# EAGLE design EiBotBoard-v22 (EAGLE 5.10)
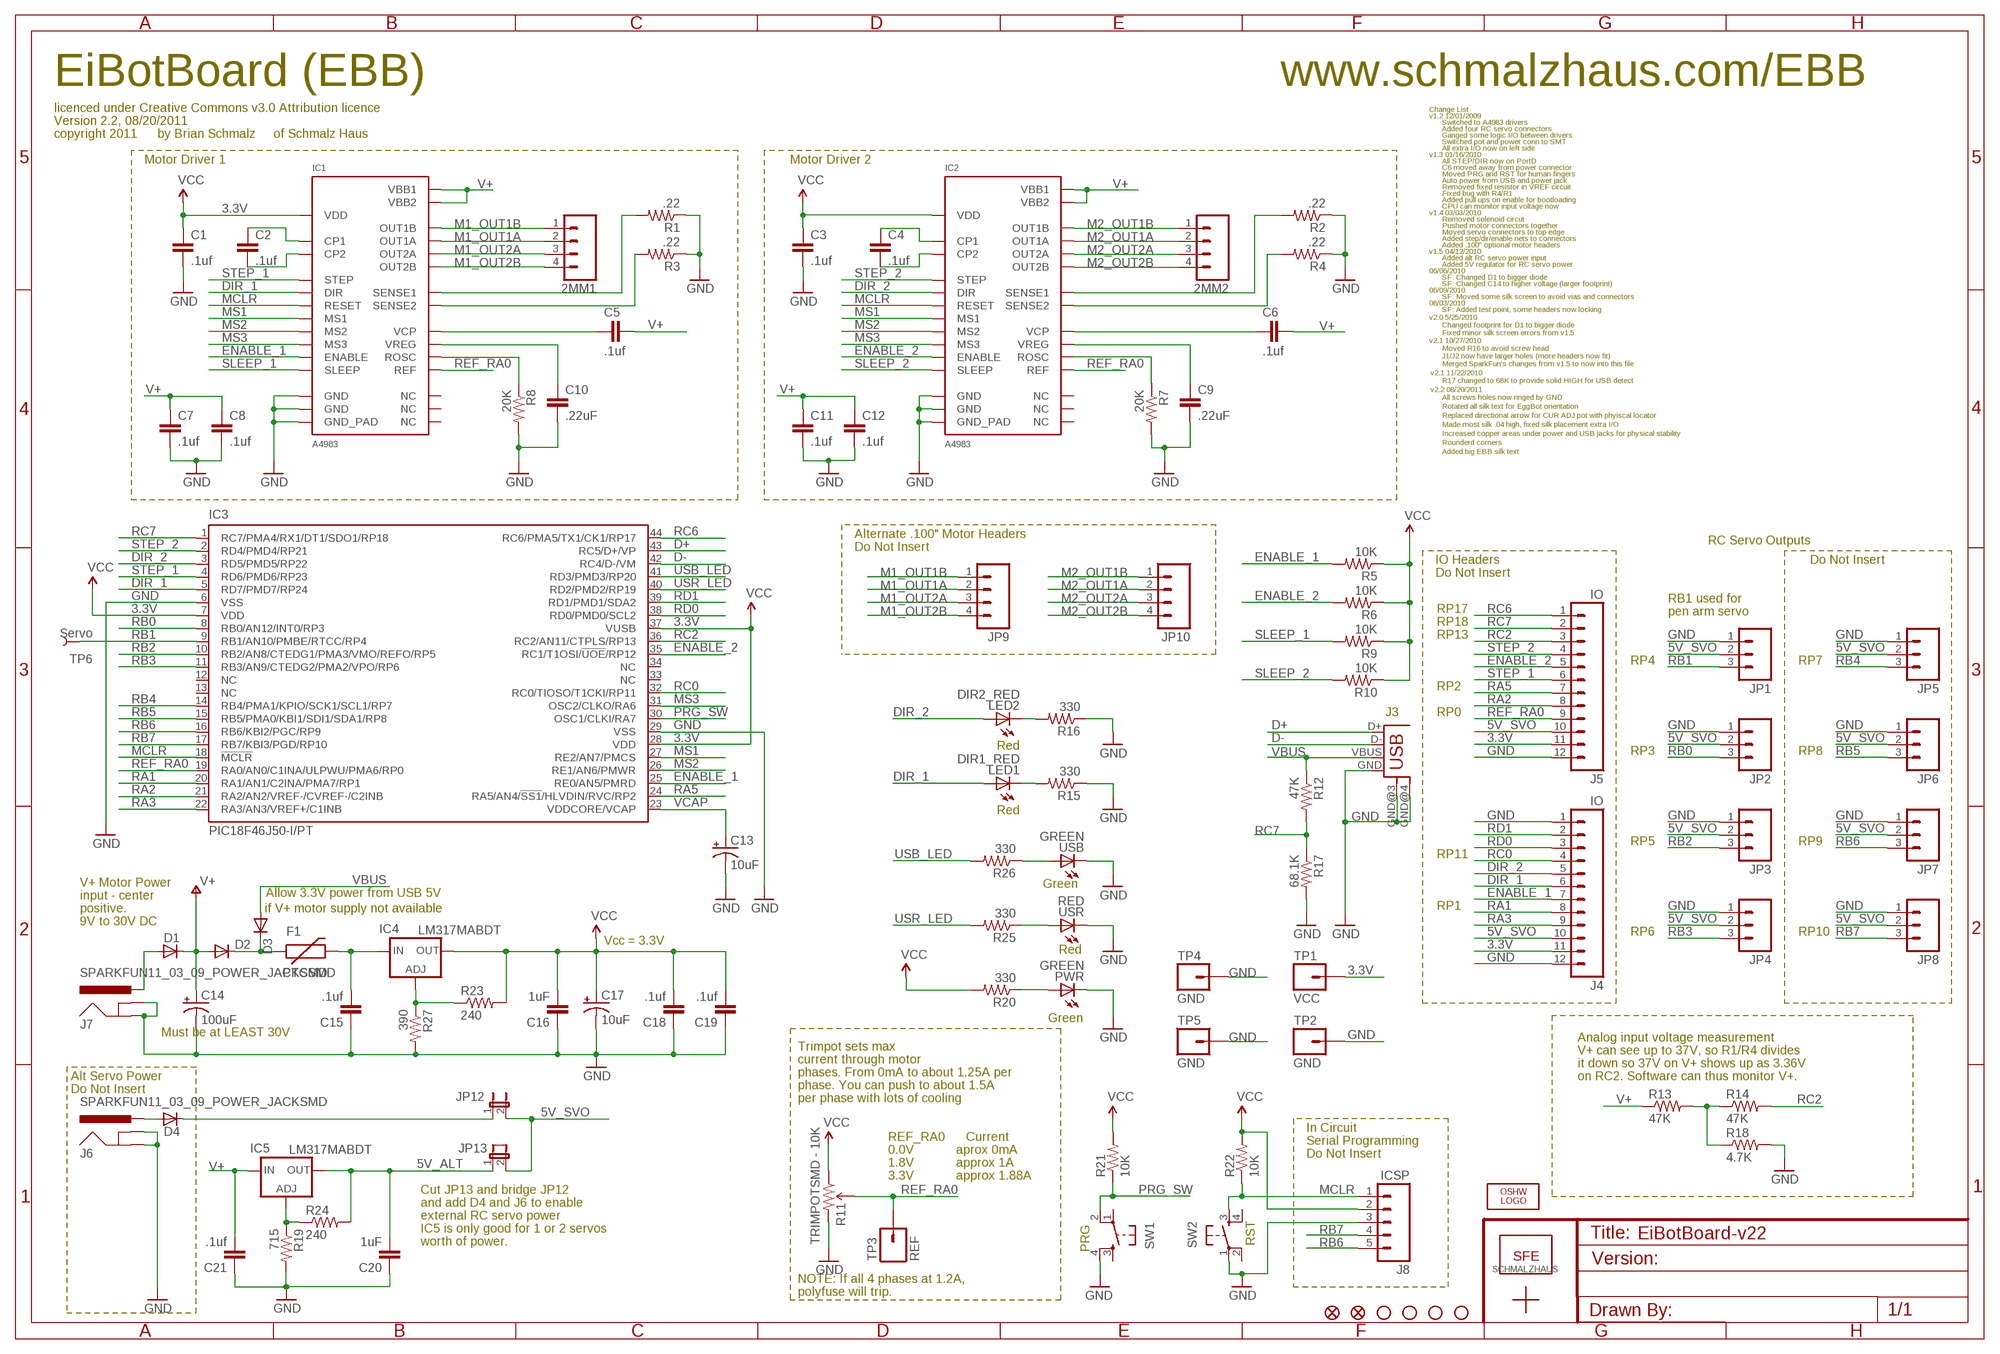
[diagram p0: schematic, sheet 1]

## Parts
2MM1  SCHMALZHAUS_M04  [SCHMALZHAUS_SCREWTERMINAL-3.5MM-4_LOCK]
2MM2  SCHMALZHAUS_M04  [SCHMALZHAUS_SCREWTERMINAL-3.5MM-4_LOCK]
C1  .1uf  CAP0603  [0603]
C2  .1uf  CAP0603  [0603]
C3  .1uf  CAP0603  [0603]
C4  .1uf  CAP0603  [0603]
C5  .1uf  CAP0603  [0603]
C6  .1uf  CAP0603  [0603]
C7  .1uf  CAP0603  [0603]
C8  .1uf  CAP0603  [0603]
C9  .22uF  CAP0603  [0603]
C10  .22uF  CAP0603  [0603]
C11  .1uf  CAP0603  [0603]
C12  .1uf  CAP0603  [0603]
C13  10uF  CAP_POL1206  [EIA3216]
C14  100uF  CAP_POLG  [PANASONIC_G]
C15  .1uf  CAP0603  [0603]
C16  1uF  CAP0603  [0603]
C17  10uF  CAP_POL1206  [EIA3216]
C18  .1uf  CAP0603  [0603]
C19  .1uf  CAP0603  [0603]
C20  1uF  CAP0603  [0603]
C21  .1uf  CAP0603  [0603]
D1  DIODE-DO214AC  [DO214AC]
D2  DIODESMA  [SMA-DIODE]
D3  DIODESMA  [SMA-DIODE]
D4  CGRM4001-G  [SOD-123_MINI-SMA]
F1  PTCSMD  [PTC-1206]
IC1  A4983  [QFN28]
IC2  A4983  [QFN28]
IC3  PIC18F46J50-I/PT  PIC18F4J50  [TQFP44]
IC4  LM317MABDT  [DPACK]
IC5  LM317MABDT  [DPACK]
J3  SCHMALZHAUS_USBSMD  [SCHMALZHAUS_USB-MINIB]
J4  IO  M12PTH  [1X12]
J5  IO  M12PTH  [1X12]
J6  SPARKFUN11_03_09_POWER_JACKSMD  [SPARKFUN11_03_09_POWER_JACK_SMD]
J7  SPARKFUN11_03_09_POWER_JACKSMD  [SPARKFUN11_03_09_POWER_JACK_SMD]
J8  ICSP  M05_WIDENOSILK  [1X05_NOSILK]
JP1  M03LOCK_NO_SILK  [1X03_LOCK_NO_SILK]
JP2  M031X03_NO_SILK  [1X03_NO_SILK]
JP3  M031X03_NO_SILK  [1X03_NO_SILK]
JP4  M031X03_NO_SILK  [1X03_NO_SILK]
JP5  M031X03_NO_SILK  [1X03_NO_SILK]
JP6  M031X03_NO_SILK  [1X03_NO_SILK]
JP7  M031X03_NO_SILK  [1X03_NO_SILK]
JP8  M031X03_NO_SILK  [1X03_NO_SILK]
JP9  M04POLAR  [MOLEX-1X4]
JP10  M04POLAR  [MOLEX-1X4]
JP11  LOGO-SFENEW  [SFE-NEW-WEBLOGO]
JP12  JUMPER-2SMD-NO  [SJ_2S-NO]
JP13  JUMPER-2SMD-NO  [SJ_2S-NO]
JP14  FIDUCIAL1X2  [FIDUCIAL-1X2]
JP15  FIDUCIAL1X2  [FIDUCIAL-1X2]
LED1  DIR1_RED  LED0603  [LED-0603]
LED2  DIR2_RED  LED0603  [LED-0603]
LOGO1  OSHW_LOGO_8MILX0100-NT  [OSHW_8X100_NOTEXT]
PWR  GREEN  LED0603  [LED-0603]
R1  .22  R-US_R0805  [R0805]
R2  .22  R-US_R0805  [R0805]
R3  .22  R-US_R0805  [R0805]
R4  .22  R-US_R0805  [R0805]
R5  10K  R-US_R0603  [R0603]
R6  10K  R-US_R0603  [R0603]
R7  20K  R-US_R0603  [R0603]
R8  20K  R-US_R0603  [R0603]
R9  10K  R-US_R0603  [R0603]
R10  10K  R-US_R0603  [R0603]
R11  TRIMPOTSMD - 10K  TRIMPOTSMD  [TRIMPOT-3MM]
R12  47K  R-US_R0603  [R0603]
R13  47K  R-US_R0603  [R0603]
R14  47K  R-US_R0603  [R0603]
R15  330  R-US_R0603  [R0603]
R16  330  R-US_R0603  [R0603]
R17  68.1K  R-US_R0603  [R0603]
R18  4.7K  R-US_R0603  [R0603]
R19  715  R-US_R0603  [R0603]
R20  330  R-US_R0603  [R0603]
R21  10K  R-US_R0603  [R0603]
R22  10K  R-US_R0603  [R0603]
R23  240  R-US_R0603  [R0603]
R24  240  R-US_R0603  [R0603]
R25  330  R-US_R0603  [R0603]
R26  330  R-US_R0603  [R0603]
R27  390  R-US_R0603  [R0603]
SW1  PRG  TAC_SWITCHSND  [TACTILE_SWITCH_SMD]
SW2  RST  TAC_SWITCHSND  [TACTILE_SWITCH_SMD]
TP1  VCC  M01_WIDENOSLIK  [1X01_NOSILK]
TP2  GND  M01_WIDENOSLIK  [1X01_NOSILK]
TP3  REF  M01PTH  [1X01]
TP4  GND  M01_WIDENOSLIK  [1X01_NOSILK]
TP5  GND  M01_WIDENOSLIK  [1X01_NOSILK]
TP6  Servo  TEST-POINT3X5  [PAD.03X.05]
U$1  SCHMALZHAUSSCHMALZHAUS_SMALL  [SCHMALZHAUS_SMALL]
U$2  STAND-OFF  [STAND-OFF]
U$3  STAND-OFF  [STAND-OFF]
U$4  STAND-OFF  [STAND-OFF]
U$5  STAND-OFF  [STAND-OFF]
USB  GREEN  LED0603  [LED-0603]
USR  RED  LED0603  [LED-0603]

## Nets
3.3V: C1.1 C3.1 C16.2 C17.A(+) C18.2 C19.2 IC1.P$15(VDD) IC2.P$15(VDD) IC3.7(VDD) IC3.28(VDD) IC3.37(VUSB) IC4.4(OUT) J4.11 J5.11 J8.2 R5.1 R6.1 R9.1 R10.1 R11.1(CCW) R20.2 R21.2 R22.2 R23.2 TP1.1 ; supply symbol labelled VCC
5V_ALT: C20.2 IC5.4(OUT) JP13.1 R24.2
5V_SVO: J4.10 J5.10 JP1.2 JP2.2 JP3.2 JP4.2 JP5.2 JP6.2 JP7.2 JP8.2 JP12.2 JP13.2
D+: IC3.43(RC5/D+/VP) J3.D+
D-: IC3.42(RC4/D-/VM) J3.D-
DIR_1: IC1.P$19(DIR) IC3.5(RD7/PMD7/RP24) J4.6 LED1.A
DIR_2: IC2.P$19(DIR) IC3.3(RD5/PMD5/RP22) J4.5 LED2.A
ENABLE_1: IC1.P$2(ENABLE) IC3.25(RE0/AN5/PMRD) J4.7 R5.2
ENABLE_2: IC2.P$2(ENABLE) IC3.35(RC1/T1OSI/!UOE!/RP12) J5.5 R6.2
GND: C1.2 C3.2 C7.2 C8.2 C9.2 C10.2 C11.2 C12.2 C13.C(-) C14.- C15.1 C16.1 C17.C(-) C18.1 C19.1 C20.1 C21.1 IC1.P$3(GND) IC1.P$18(GND) IC1.P$29(GND_PAD) IC2.P$3(GND) IC2.P$18(GND) IC2.P$29(GND_PAD) IC3.6(VSS) IC3.29(VSS) J3.GND J3.GND@3(GND) J3.GND@4(GND) J4.1 J4.12 J5.12 J6.GND(GNDBREAK) J6.P$4(GND) J7.GND(GNDBREAK) J7.P$4(GND) J8.3 JP1.1 JP2.1 JP3.1 JP4.1 JP5.1 JP6.1 JP7.1 JP8.1 PWR.C R1.1 R2.1 R3.1 R4.1 R7.2 R8.2 R11.3(CW) R15.1 R16.1 R17.2 R18.2 R19.2 R27.2 SW1.4 SW2.1 TP2.1 TP4.1 TP5.1 USB.C USR.C
M1_OUT1A: 2MM1.2 IC1.P$24(OUT1A) JP9.2
M1_OUT1B: 2MM1.1 IC1.P$21(OUT1B) JP9.1
M1_OUT2A: 2MM1.3 IC1.P$26(OUT2A) JP9.3
M1_OUT2B: 2MM1.4 IC1.P$1(OUT2B) JP9.4
M2_OUT1A: 2MM2.2 IC2.P$24(OUT1A) JP10.2
M2_OUT1B: 2MM2.1 IC2.P$21(OUT1B) JP10.1
M2_OUT2A: 2MM2.3 IC2.P$26(OUT2A) JP10.3
M2_OUT2B: 2MM2.4 IC2.P$1(OUT2B) JP10.4
MCLR: IC1.P$12(RESET) IC2.P$12(RESET) IC3.18(!MCLR!) J8.1 R22.1 SW2.3
MS1: IC1.P$9(MS1) IC2.P$9(MS1) IC3.27(RE2/AN7/PMCS)
MS2: IC1.P$10(MS2) IC2.P$10(MS2) IC3.26(RE1/AN6/PMWR)
MS3: IC1.P$11(MS3) IC2.P$11(MS3) IC3.31(OSC2/CLKO/RA6)
N$2: D2.C D3.C F1.1
N$3: C2.1 IC1.P$4(CP1)
N$4: R13.2 R14.1 R18.1
N$5: C2.2 IC1.P$5(CP2)
N$6: D1.A J7.VIN0(PWR)
N$7: D4.A J6.VIN0(PWR)
N$8: IC5.1(ADJ) R19.1 R24.1
N$9: IC4.1(ADJ) R23.1 R27.1
N$10: D4.C JP12.1
N$16: C4.1 IC2.P$4(CP1)
N$17: C4.2 IC2.P$5(CP2)
N$19: IC1.P$13(ROSC) R8.1
N$20: C10.1 IC1.P$8(VREG)
N$21: C5.1 IC1.P$6(VCP)
N$26: LED2.C R16.2
N$27: PWR.A R20.1
N$29: R26.1 USB.A
N$30: R25.1 USR.A
N$31: IC1.P$27(SENSE2) R3.2
N$32: IC1.P$23(SENSE1) R1.2
N$35: LED1.C R15.2
N$36: C15.2 F1.2 IC4.3(IN)
N$41: C6.1 IC2.P$6(VCP)
N$43: IC2.P$23(SENSE1) R2.2
N$44: IC2.P$27(SENSE2) R4.2
N$45: C9.1 IC2.P$8(VREG)
N$48: IC2.P$13(ROSC) R7.1
PRG_SW: IC3.30(OSC1/CLKI/RA7) R21.1 SW1.2
RA1: IC3.20(RA1/AN1/C2INA/PMA7/RP1) J4.8
RA2: IC3.21(RA2/AN2/VREF-/CVREF-/C2INB) J5.8
RA3: IC3.22(RA3/AN3/VREF+/C1INB) J4.9
RA5: IC3.24(RA5/AN4/!SS1!/HLVDIN/RVC/RP2) J5.7
RB0: IC3.8(RB0/AN12/INT0/RP3) JP2.3
RB1: IC3.9(RB1/AN10/PMBE/RTCC/RP4) JP1.3 TP6.P$1
RB2: IC3.10(RB2/AN8/CTEDG1/PMA3/VMO/REFO/RP5) JP3.3
RB3: IC3.11(RB3/AN9/CTEDG2/PMA2/VPO/RP6) JP4.3
RB4: IC3.14(RB4/PMA1/KPIO/SCK1/SCL1/RP7) JP5.3
RB5: IC3.15(RB5/PMA0/KBI1/SDI1/SDA1/RP8) JP6.3
RB6: IC3.16(RB6/KBI2/PGC/RP9) J8.5 JP7.3
RB7: IC3.17(RB7/KBI3/PGD/RP10) J8.4 JP8.3
RC0: IC3.32(RC0/TIOSO/T1CKI/RP11) J4.4
RC2: IC3.36(RC2/AN11/CTPLS/RP13) J5.3 R14.2
RC6: IC3.44(RC6/PMA5/TX1/CK1/RP17) J5.1
RC7: IC3.1(RC7/PMA4/RX1/DT1/SDO1/RP18) J5.2 R12.2 R17.1
RD0: IC3.38(RD0/PMD0/SCL2) J4.3
RD1: IC3.39(RD1/PMD1/SDA2) J4.2
REF_RA0: IC1.P$17(REF) IC2.P$17(REF) IC3.19(RA0/AN0/C1INA/ULPWU/PMA6/RP0) J5.9 R11.2(WIPER) TP3.1
SLEEP_1: IC1.P$14(SLEEP) R9.2
SLEEP_2: IC2.P$14(SLEEP) R10.2
STEP_1: IC1.P$16(STEP) IC3.4(RD6/PMD6/RP23) J5.6
STEP_2: IC2.P$16(STEP) IC3.2(RD4/PMD4/RP21) J5.4
USB_LED: IC3.41(RD3/PMD3/RP20) R26.2
USR_LED: IC3.40(RD2/PMD2/RP19) R25.2
V+: C5.2 C6.2 C7.1 C8.1 C11.1 C12.1 C14.+ C21.2 D1.C D2.A IC1.P$22(VBB1) IC1.P$28(VBB2) IC2.P$22(VBB1) IC2.P$28(VBB2) IC5.3(IN) R13.1
VBUS: D3.A J3.VBUS R12.1
VCAP: C13.A(+) IC3.23(VDDCORE/VCAP)
Unconnected: IC1.P$7(NC) IC1.P$20(NC) IC1.P$25(NC) IC2.P$7(NC) IC2.P$20(NC) IC2.P$25(NC) IC3.12(NC) IC3.13(NC) IC3.33(NC) IC3.34(NC) SW1.1 SW1.3 SW2.2 SW2.4

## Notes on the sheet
- EiBotBoard (EBB) | www.schmalzhaus.com/EBB
- licenced under Creative Commons v3.0 Attribution licence | Change List
- v1.2 12/01/2009
- Version 2.2, 08/20/2011 | Switched to A4983 drivers
- Added four RC servo connectors
- copyright 2011 | by Brian Schmalz | of Schmalz Haus | Ganged some logic I/O between drivers
- Switched pot and power conn to SMT
- All extra I/O now on left side
- v1.3 01/16/2010
- Motor Driver 1 | Motor Driver 2 | All STEP/DIR now on PortD
- C6 moved away from power connector
- Moved PRG and RST for human fingers
- Auto power from USB and power jack
- Removed fixed resistor in VREF circuit
- Fixed bug with R4/R1
- Added pull ups on enable for bootloading
- CPU can monitor input voltage now
- v1.4 03/03/2010
- Removed solenoid circut
- Pushed motor connectors together
- Moved servo connectors to top edge
- Added step/dir/enable nets to connectors
- Added .100" optional motor headers
- v1.5 04/12/2010
- Added alt RC servo power input
- Added 5V regulator for RC servo power
- 06/06/2010
- SF: Changed D1 to bigger diode
- SF: Changed C14 to higher voltage (larger footprint)
- 06/09/2010
- SF: Moved some silk screen to avoid vias and connectors
- 08/03/2010
- SF: Added test point, some headers now locking
- v2.0 5/25/2010
- Changed footprint for D1 to bigger diode
- Fixed minor silk screen errors from v1.5
- v2.1 10/27/2010
- Moved R16 to avoid screw head
- J1/J2 now have larger holes (more headers now fit)
- Merged SparkFun's changes from v1.5 to now into this file
- v2.1 11/22/2010
- R17 changed to 68K to provide solid HIGH for USB detect
- v2.2 08/20/2011
- All screws holes now ringed by GND
- Rotated all silk text for EggBot orientation
- Replaced directional arrow for CUR ADJ pot with phyiscal locator
- Made most silk .04 high, fixed silk placement extra I/O
- Increased copper areas under power and USB jacks for physical stability
- Rounderd corners
- Added big EBB silk text
- Alternate .100" Motor Headers
- RC Servo Outputs
- Do Not Insert
- IO Headers | Do Not Insert
- Do Not Insert
- RB1 used for
- RP17 | pen arm servo
- RP18
- RP13
- RP4 | RP7
- RP2
- J3 | RP0
- Red
- RP3 | RP8
- Red
- RP5 | RP9
- RP11
- V+ Motor Power | Green
- input - center | Allow 3.3V power from USB 5V
- positive. | if V+ motor supply not available | RP1
- 9V to 30V DC
- RP6 | RP10
- Vcc = 3.3V | Red
- Green
- Must be at LEAST 30V
- Analog input voltage measurement
- Trimpot sets max
- V+ can see up to 37V, so R1/R4 divides
- current through motor
- it down so 37V on V+ shows up as 3.36V
- phases. From 0mA to about 1.25A per
- Alt Servo Power | on RC2. Software can thus monitor V+.
- phase. You can push to about 1.5A
- Do Not Insert
- per phase with lots of cooling
- In Circuit
- REF_RA0      Current
- Serial Programming
- 0.0V            aprox 0mA
- Do Not Insert
- 1.8V            approx 1A
- 3.3V            approx 1.88A
- Cut JP13 and bridge JP12
- and add D4 and J6 to enable
- external RC servo power
- PRG
- IC5 is only good for 1 or 2 servos
- worth of power. | RST
- NOTE: If all 4 phases at 1.2A,
- polyfuse will trip.

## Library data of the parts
2MM1 2MM2 = EiBotBoard-v21:SCHMALZHAUS_M04: Header 4 Standard 4-pin 0.1" header. Use with straight break away headers (SKU : PRT-00116), right angle break away headers (PRT-00553), swiss pins (PRT-00743), machine pins (PRT-00117), and female headers (PRT-00115). Molex polarized connector foot print use with SKU : PRT-08231 with associated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
C1-C12 C15 C16 C18-C21 = SparkFun-2-11-09:CAP: Capacitor
C13 C17 = SparkFun-2-11-09:CAP_POL: Capacitor Polarized
C14 = SparkFun:CAP_POL: Capacitor Polarized
D1 = diode:DIODE-: DIODE
D2 D3 = SparkFun:DIODE: Diode
D4 = diode:CGRM400*-G: Molded plasitc,JEDEC SOD-123/Mini SMA
F1 = SchmalzHaus:PTC: Resettable Fuse PTC
IC1 IC2 = SchmalzHaus:A4983
IC3 = SchmalzHaus:PIC18F4*J50
IC4 IC5 = v-reg:LM317?*: 500 mA Adjustable Output Positive Voltage Regulator Source: http://www.onsemi.co.jp .. LM317M-D.PDF
J3 = EiBotBoard-v22:SCHMALZHAUS_USB: USB Connectors USB-B-PTH is fully proven SKU : PRT-00139 USB-miniB is fully proven SKU : PRT-00587 USB-A-PCB is untested. USB-A-H is throughly reviewed, but untested. Spark Fun Electronics SKU : PRT-00437 USB-B-SMT is throughly reviewed, but untested. Needs silkscreen touching up. USB-A-S has not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
J4 J5 = SparkFun-12-01-09:M12: Header 12 Standard 12-pin 0.1" header. Use with straight break away headers (SKU : PRT-00116), right angle break away headers (PRT-00553), swiss pins (PRT-00743), machine pins (PRT-00117), and female headers (PRT-00115).
J6 J7 = EiBotBoard-v22:SPARKFUN11_03_09_POWER_JACK: Power Jack This is the standard 5.5mm barrel jack for power. The PTH is the most common, proven, reliable, footprint. All others are experimental. The Slot footprint only works if the mill layer is transmitted to the PCB fab house so be warned. Spark Fun Electronics SKU : PRT-00119. Mating wall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
J8 = SchmalzHaus:M05_WIDE: Header 5 Standard 5-pin 0.1" header. Use with straight break away headers (SKU : PRT-00116), right angle break away headers (PRT-00553), swiss pins (PRT-00743), machine pins (PRT-00117), and female headers (PRT-00115). Molex polarized connector foot print use with SKU : PRT-08230 with associated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
JP1 = SparkFun:M03: Header 3 Standard 3-pin 0.1" header. Use with straight break away headers (SKU : PRT-00116), right angle break away headers (PRT-00553), swiss pins (PRT-00743), machine pins (PRT-00117), and female headers (PRT-00115). Molex polarized connector foot print use with SKU : PRT-08232 with associated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
JP2-JP8 = SparkFun-12-01-09:M03: Header 3 Standard 3-pin 0.1" header. Use with straight break away headers (SKU : PRT-00116), right angle break away headers (PRT-00553), swiss pins (PRT-00743), machine pins (PRT-00117), and female headers (PRT-00115). Molex polarized connector foot print use with SKU : PRT-08232 with associated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
JP9 JP10 = SparkFun-12-01-09:M04: Header 4 Standard 4-pin 0.1" header. Use with straight break away headers (SKU : PRT-00116), right angle break away headers (PRT-00553), swiss pins (PRT-00743), machine pins (PRT-00117), and female headers (PRT-00115). Molex polarized connector foot print use with SKU : PRT-08231 with associated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
JP11 = SparkFun-12-01-09:LOGO-SFE: Spark Fun Electronics PCB Logo
JP12 JP13 = SparkFun-12-01-09:JUMPER-2: Jumper
JP14 JP15 = SparkFun:FIDUCIAL: Fiducial Alignment Points
LED1 LED2 PWR USB USR = SparkFun-2-11-09:LED: LEDs
LOGO1 = OSHW:OSHW_LOGO_8MIL
R1-R10 R12-R27 = rcl:R-US_: RESISTOR, American symbol
R11 = SparkFun11_03_09:TRIMPOT
SW1 SW2 = SparkFunEagle-6-6-07:TAC_SWITCH: Momentary Switch Button commonly used for reset or general input. Spark Fun Electronics SKU : COM-00097
TP1 TP2 TP4 TP5 = SchmalzHaus:M01_WIDE: Header 1
TP3 = SchmalzHaus:M01: Header 1
TP6 = SparkFun:TEST-POINT
U$1 = SchmalzHaus:SCHMALZHAUS
U$2-U$5 = SparkFun01082009:STAND-OFF: Stand Off

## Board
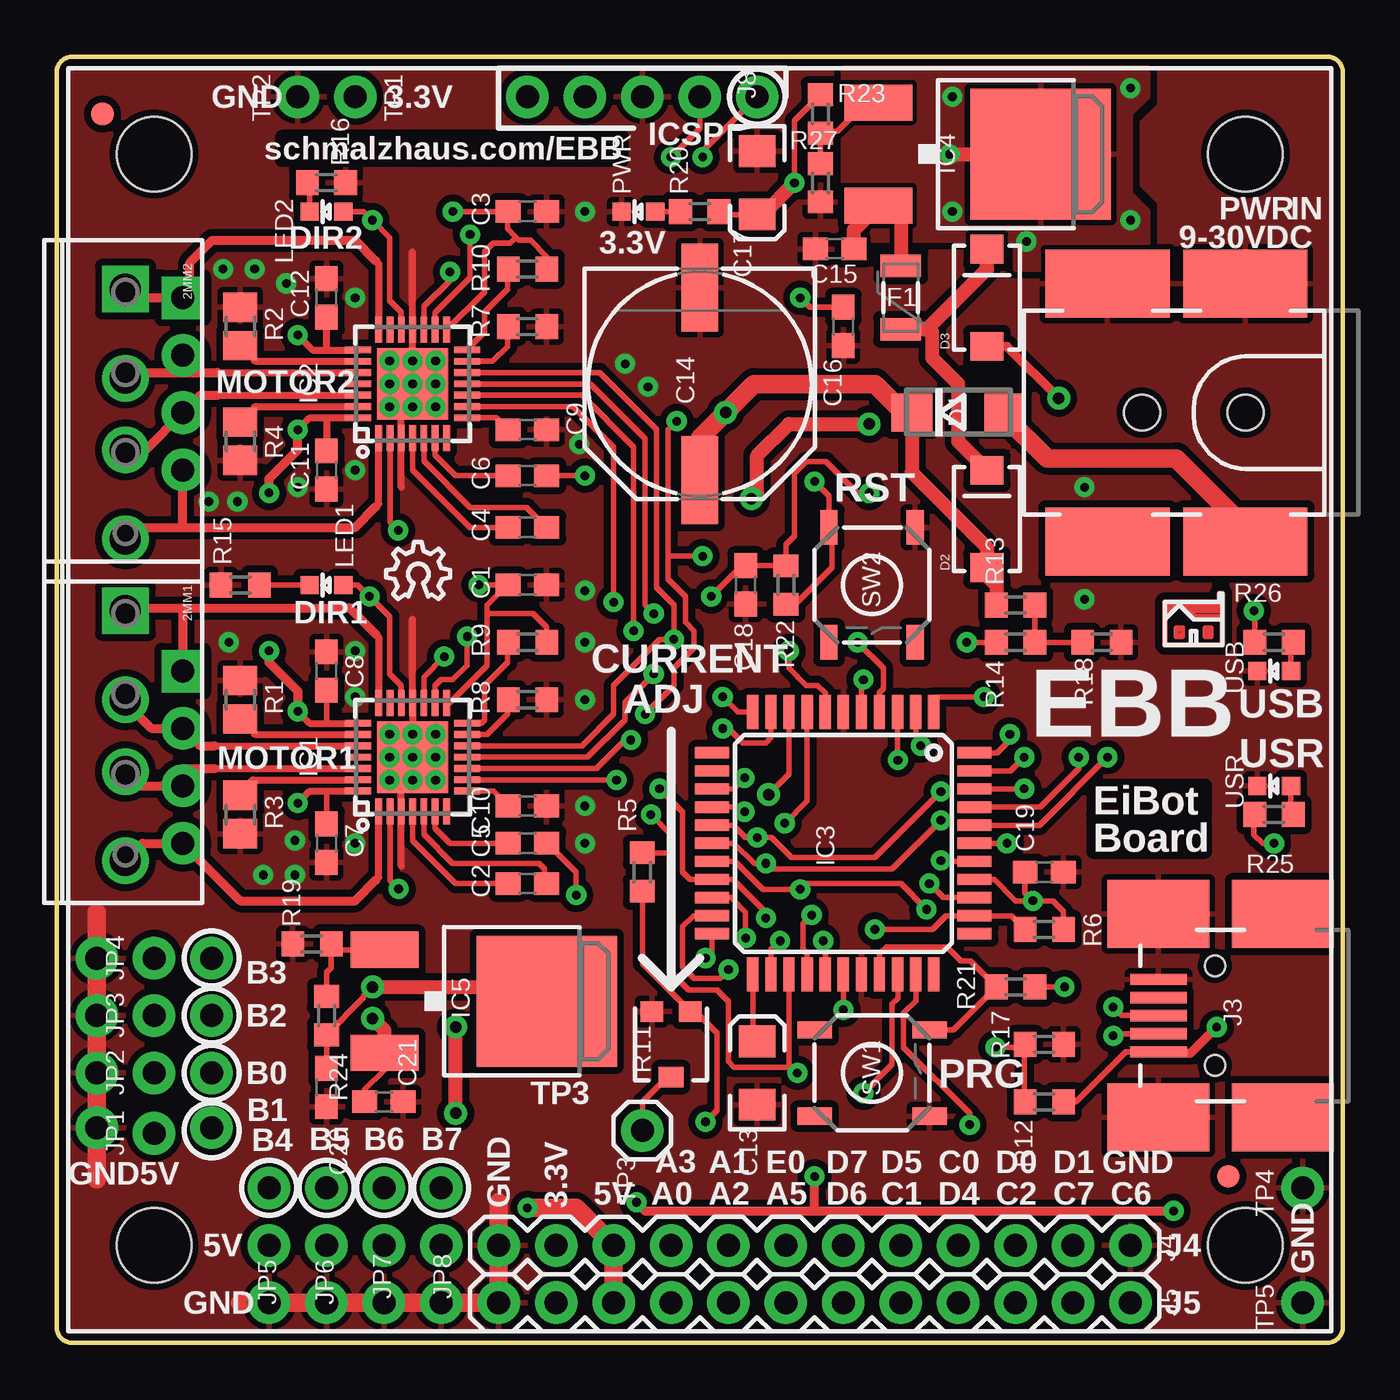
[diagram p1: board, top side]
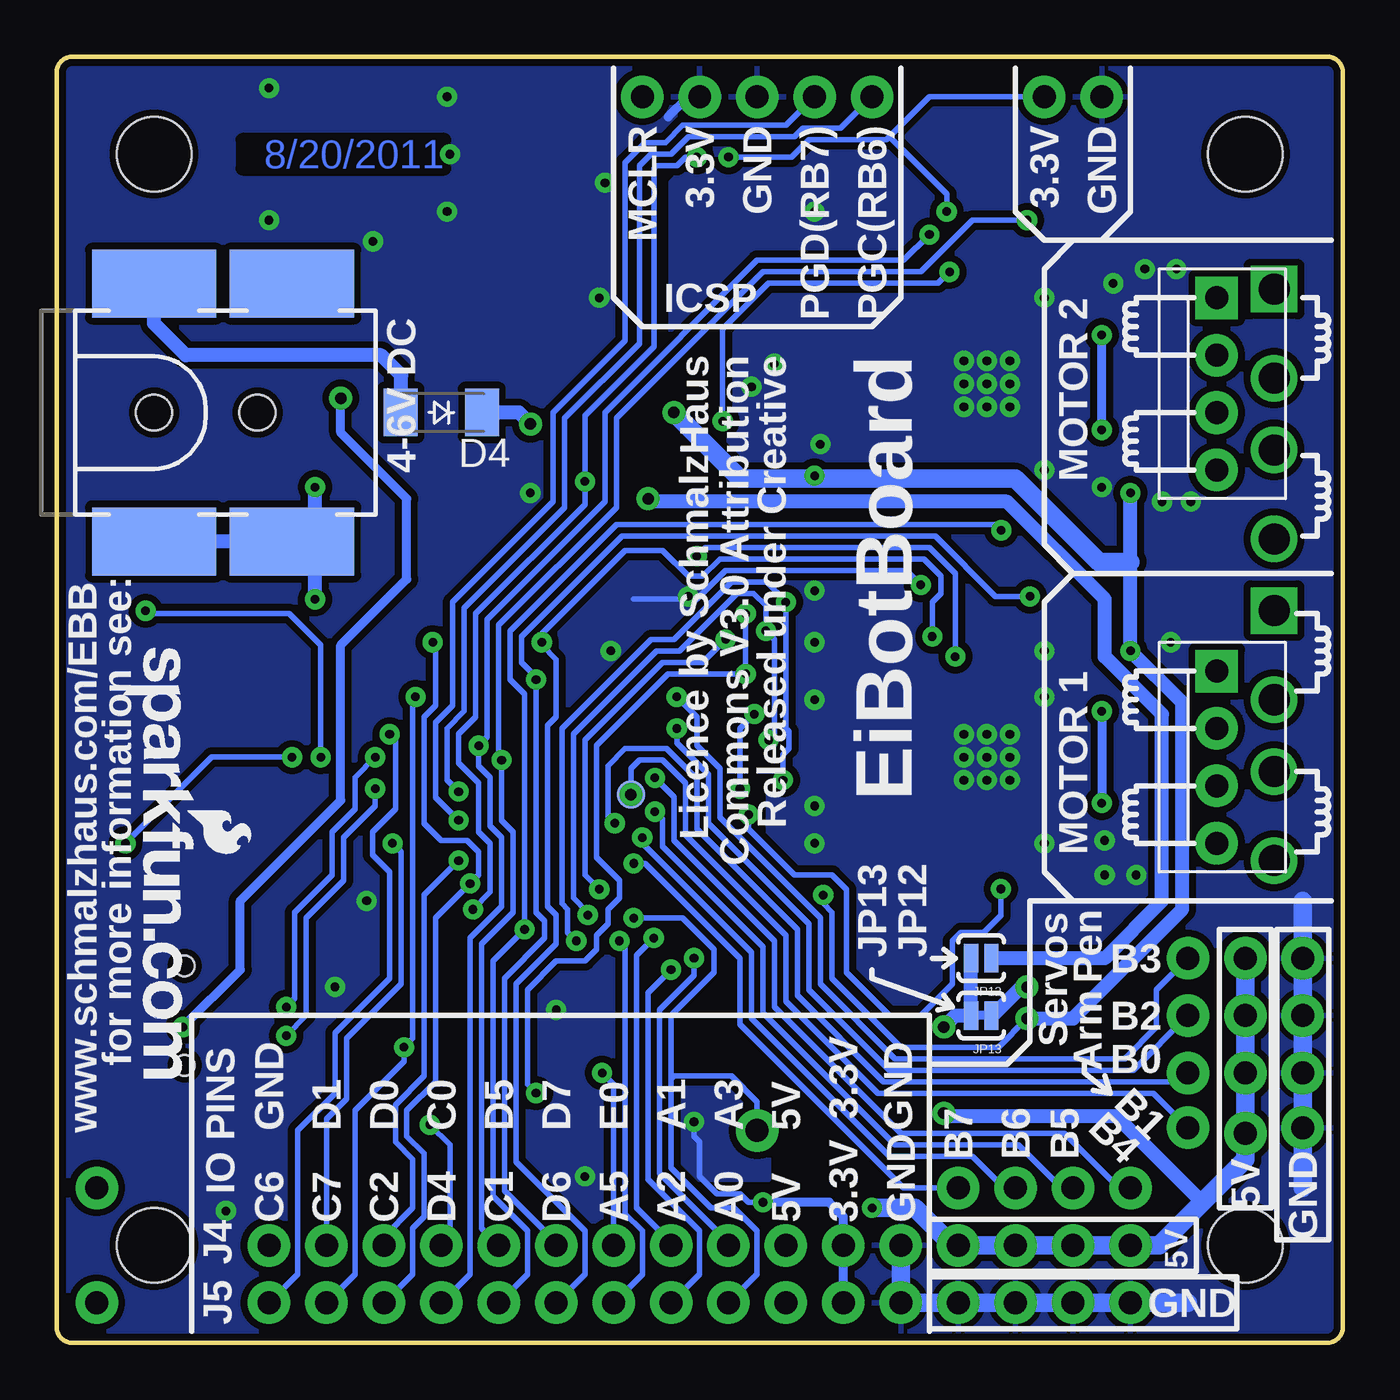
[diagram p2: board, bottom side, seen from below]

Size 56.9 x 56.9 mm. Coordinates in mm from the lower left corner, seen from the top.
Outline: 56.9,56.18 arc90 56.18,56.9 0.72,56.9 arc90 0,56.18 0,0.72 arc90 0.72,0 56.18,0 arc90 56.9,0.72 56.9,56.18
Copper layers (1*16): Top 0.035mm / dielectric 1.5mm / Bottom 0.035mm
Design rules "SparkFun *": minimum track width 8mil, minimum drill 15mil, track to track 8mil, track to pad 8mil, pad to pad 8mil, via to via 8mil, smd to smd 8mil, copper to edge 8mil, drill to drill 8mil, minimum pad ring 12mil, minimum via ring 10mil, stop-mask expansion 4mil, vias tented up to drill 20mil, thermal gap 10mil

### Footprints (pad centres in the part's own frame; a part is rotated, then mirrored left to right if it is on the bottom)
SCHMALZHAUS_SCREWTERMINAL-3.5MM-4_LOCK = drill 1.372 square: 1 -0.127,0 | drill 1.372 round: 2 3.81,0; 3 6.985,0; 4 10.922,0
0603 = smd 1.1 x 1: 1 -0.85,0; 2 0.85,0
EIA3216 = smd 1.4 x 1.6: A 1.4,0; C -1.4,0
PANASONIC_G = smd 3.9 x 1.6: + 4.25,0; - -4.25,0
DO214AC = smd 1.8 x 1.7: A 2.05,0; C -2.05,0
SMA-DIODE = smd 1.27 x 1.47: A -2.15,0; C 2.15,0
SOD-123_MINI-SMA = smd 1.5 x 2.1: A 1.8,0; C -1.8,0
PTC-1206 = smd 1 x 1.8: 1 -1.4,0; 2 1.4,0
QFN28 = smd 1.15 x 0.3: P$1 -2.4,1.5; P$2 -2.4,1; P$3 -2.4,0.5; P$4 -2.4,0; P$5 -2.4,-0.5; P$6 -2.4,-1; P$7 -2.4,-1.5; P$15 2.4,-1.5; P$16 2.4,-1; P$17 2.4,-0.5; P$18 2.4,0; P$19 2.4,0.5; P$20 2.4,1; P$21 2.4,1.5 | smd 0.3 x 1.15: P$8 -1.5,-2.4; P$9 -1,-2.4; P$10 -0.5,-2.4; P$11 0,-2.4; P$12 0.5,-2.4; P$13 1,-2.4; P$14 1.5,-2.4; P$22 1.5,2.4; P$23 1,2.4; P$24 0.5,2.4; P$25 0,2.4; P$26 -0.5,2.4; P$27 -1,2.4; P$28 -1.5,2.4 | smd 3.15 x 3.15: P$29 0,0
TQFP44 = smd 1.5 x 0.5: 1 -5.8,4; 2 -5.8,3.2; 3 -5.8,2.4; 4 -5.8,1.6; 5 -5.8,0.8; 6 -5.8,0; 7 -5.8,-0.8; 8 -5.8,-1.6; 9 -5.8,-2.4; 10 -5.8,-3.2; 11 -5.8,-4; 23 5.8,-4; 24 5.8,-3.2; 25 5.8,-2.4; 26 5.8,-1.6; 27 5.8,-0.8; 28 5.8,0; 29 5.8,0.8; 30 5.8,1.6; 31 5.8,2.4; 32 5.8,3.2; 33 5.8,4 | smd 0.5 x 1.5: 12 -4,-5.8; 13 -3.2,-5.8; 14 -2.4,-5.8; 15 -1.6,-5.8; 16 -0.8,-5.8; 17 0,-5.8; 18 0.8,-5.8; 19 1.6,-5.8; 20 2.4,-5.8; 21 3.2,-5.8; 22 4,-5.8; 34 4,5.8; 35 3.2,5.8; 36 2.4,5.8; 37 1.6,5.8; 38 0.8,5.8; 39 0,5.8; 40 -0.8,5.8; 41 -1.6,5.8; 42 -2.4,5.8; 43 -3.2,5.8; 44 -4,5.8
DPACK = smd 1.6 x 3: 1 -2.28,-4.8; 3 2.28,-4.8 | smd 5.8 x 6.2: 4 0,2.38
SCHMALZHAUS_USB-MINIB = smd 2.5 x 0.5: D+ 2.5,0; D- 2.5,0.8; GND 2.5,-1.6; ID 2.5,-0.8; VBUS 2.5,1.6 | smd 4.5 x 3: GND@1 -3,-4.5; GND@2 -3,4.5; GND@3 2.5,4.5; GND@4 2.5,-4.5 | hole 0.9: 0,2.2; 0,-2.2
1X12 = drill 1.016 pad 1.88 round: 1 0,0; 2 2.54,0; 3 5.08,0; 4 7.62,0; 5 10.16,0; 6 12.7,0; 7 15.24,0; 8 17.78,0; 9 20.32,0; 10 22.86,0; 11 25.4,0; 12 27.94,0
SPARKFUN11_03_09_POWER_JACK_SMD = smd 5.5 x 3: GND 0,-5.7; P$4 6.1,-5.7; VIN0 0,5.7; VIN1 6.1,5.7 | hole 1.6: 0,0; 4.572,0
1X05_NOSILK = drill 1.016 pad 1.88 round: 1 0,0; 2 2.54,0; 3 5.08,0; 4 7.62,0; 5 10.16,0
1X03_LOCK_NO_SILK = drill 1.016 pad 1.88 round: 1 0,0.127; 2 2.54,-0.127; 3 5.08,0.127
1X03_NO_SILK = drill 1.016 pad 1.88 round: 1 0,0; 2 2.54,0; 3 5.08,0
MOLEX-1X4 = drill 1.016 pad 1.88 square: 1 0,0 | drill 1.016 pad 1.88 round: 2 2.54,0; 3 5.08,0; 4 7.62,0
SJ_2S-NO = smd 0.635 x 1.27: 1 -0.45,0; 2 0.45,0
FIDUCIAL-1X2 = smd 1 x 1: 1 0,0
LED-0603 = smd 0.8 x 0.8: A 0,-0.75; C 0,0.75
R0805 = smd 1.3 x 1.5: 1 -0.85,0; 2 0.85,0
R0603 = smd 1 x 1.1: 1 -0.85,0; 2 0.85,0
TRIMPOT-3MM = smd 1 x 0.9: 1 -0.85,-1.45; 3 0.85,-1.45 | smd 1.1 x 0.9: 2 0,1.45
TACTILE_SWITCH_SMD = smd 1.524 x 0.762: 1 -2.54,1.905; 2 2.54,1.905; 3 -2.54,-1.905; 4 2.54,-1.905
1X01_NOSILK = drill 1.016 pad 1.88 round: 1 0,0
1X01 = drill 1.016 pad 1.88 round: 1 0,0
PAD.03X.05 = smd 1.27 x 1.27: P$1 0,0
STAND-OFF = hole 3.302: 0,0

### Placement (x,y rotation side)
2MM1  3.05,32.26 270 top
2MM2  3.05,46.48 270 top
C1  20.83,33.53 0 top
C2  20.83,20.32 0 top
C3  20.83,50.04 0 top
C4  20.83,36.07 0 top
C5  20.83,22.1 0 top
C6  20.83,38.35 0 top
C7  11.94,22.1 270 top
C8  11.94,29.72 90 top
C9  20.83,40.39 0 top
C10  20.83,23.75 0 top
C11  11.94,38.61 270 top
C12  11.94,46.23 90 top
C13  30.99,11.94 90 top
C14  28.45,42.42 270 top
C15  34.42,48.39 0 top
C16  34.8,44.96 90 top
C17  30.99,51.31 270 top
C18  30.48,33.53 90 top
C19  43.69,20.83 180 top
C20  11.94,11.3 90 top
C21  14.48,10.67 180 top
D1  39.88,41.15 0 top
D2  41.15,36.45 90 top
D3  41.15,46.23 90 top
D4  39.88,41.15 180 bottom
F1  37.34,46.23 90 top
IC1  15.75,25.91 90 top
IC2  15.75,42.42 90 top
IC3  34.8,22.1 270 top
IC4  41.15,52.58 270 top
IC5  19.3,15.11 270 top
J3  51.23,14.48 180 top
J4  47.5,4.32 180 top
J5  47.5,1.78 180 top
J6  52.58,41.15 0 bottom
J7  52.58,41.15 180 top
J8  30.99,55.12 180 top
JP1  1.78,9.4 0 top
JP2  1.78,11.94 0 top
JP3  1.78,14.48 0 top
JP4  1.78,17.02 0 top
JP5  9.4,1.78 90 top
JP6  11.94,1.78 90 top
JP7  14.48,1.78 90 top
JP8  17.02,1.78 90 top
JP9  5.59,29.72 270 bottom
JP10  5.59,46.23 270 bottom
JP11  53.98,30.73 270 bottom
JP12  16,17.02 180 bottom
JP13  16,14.48 180 bottom
JP14  2.03,54.36 90 top
JP15  51.82,7.37 90 top
LED1  11.94,33.53 90 top
LED2  11.94,50.04 90 top
LOGO1  14.58,32.89 0 top
PWR  25.73,50.04 90 top
R1  8.13,28.45 270 top
R2  8.13,44.96 270 top
R3  8.13,23.37 90 top
R4  8.13,39.88 90 top
R5  25.91,20.83 90 top
R6  43.69,18.29 180 top
R7  20.83,44.96 0 top
R8  20.83,28.45 0 top
R9  20.83,30.99 180 top
R10  20.83,47.5 180 top
R11  27.18,13.21 180 top
R12  43.69,10.67 180 top
R13  42.42,32.64 0 top
R14  42.42,30.99 180 top
R15  8.13,33.53 0 top
R16  11.94,51.31 180 top
R17  43.69,13.21 0 top
R18  46.23,30.99 0 top
R19  11.3,17.65 180 top
R20  28.45,50.04 0 top
R21  42.42,15.75 0 top
R22  32.26,33.53 90 top
R23  33.78,54.36 90 top
R24  11.94,14.48 270 top
R25  53.85,23.37 180 top
R26  53.85,30.99 180 top
R27  33.78,51.31 270 top
SW1  36.07,11.94 0 top
SW2  36.07,33.53 270 top
TP1  13.21,55.12 90 top
TP2  10.67,55.12 90 top
TP3  25.91,9.4 90 top
TP4  55.12,6.86 90 top
TP5  55.12,1.78 90 top
TP6  31.5,24.26 270 bottom
U$1  50.29,30.86 0 top
U$2  52.58,52.58 90 top
U$3  52.58,4.32 90 top
U$4  4.32,52.58 90 top
U$5  4.32,4.32 90 top
USB  53.85,29.72 90 top
USR  53.85,24.64 90 top

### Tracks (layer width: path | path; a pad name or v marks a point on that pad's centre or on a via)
3.3V  (via drill 0.38)
  Top 0.254: IC1.P$15 17.39,28.31 19.05,29.97 19.05,32.26 | 19.05,32.26 19.05,32.64 19.94,33.53 C1.1 v18.67,33.53 | 19.94,50 19.94,49.28 20.32,48.9 | IC3.37 41.48,20.5 42.42,19.56 v43.18,19.56 | R10.1 21.68,48.05 20.95,48.77 20.45,48.77 20.32,48.9 | R9.1 21.68,31.66 21.08,32.26 19.05,32.26 | C3.1 v17.53,50.04 | R21.2 v44.58,15.75 44.54,15.79 | v43.18,19.56 42.84,19.9 C19.2 | R6.1 44.54,19.09 44.07,19.56 v43.18,19.56 | IC3.7 34,28.74 33.66,29.08 33.15,29.08 32.38,29.84 v32.38,30.61 | v34.8,14.73 IC3.28 | v27.18,52.45 28.45,53.72 J8.2 | 20.32,48.9 20.07,48.64 19.3,48.64 18.92,48.26 18.92,46.48 17.26,44.82 IC2.P$15 | R5.1 25.91,16.78 R11.1 28.27,14.66 29.21,13.72 29.21,10.29 v28.7,9.78 | v35.94,37.59 35.43,37.59 34.04,38.99 33.15,38.99 32.64,38.48 32.64,35.69 32.26,35.31 R22.2 C18.2 30.31,34.38 v28.96,33.02 | C16.2 33.31,45.81 v32.89,46.23 | R20.2 29.43,49.91 C17.A 31.24,49.91 | v32.64,51.31 32.64,54.06 R23.2
  Top 0.305: 19.94,50 C3.1
  Top 0.406: 33.53,5.84 v49.4,5.84 | 33.53,5.84 v33.53,7.37 | 33.53,5.84 26.04,5.84 v25.65,6.22
  Top 0.61: v39.5,52.58 IC4.4 | 31.24,49.91 v32.64,51.31
  Bottom 0.254: v18.67,33.53 19.3,34.16 27.3,34.16 28.57,32.89 31.37,32.89 | v27.18,52.45 24.38,52.45 23.62,53.21 20.19,53.21 20.07,53.34 | 20.07,53.34 18.29,55.12 TP1.1 | v17.53,50.04 17.53,50.8 20.07,53.34 | 22.73,6.22 24.38,6.22 | v25.65,6.22 26.29,6.22 26.67,6.6 27.69,6.6 28.45,7.37 28.45,8.89 28.7,9.14 v28.7,9.78
  Bottom 0.406: J5.11 J4.11 22.1,5.59 22.73,6.22 v25.65,6.22 | J8.2 28.96,55.12 29.84,54.23
  other vias: 42.9,48.72 47.5,55.5 47.5,49.66 39.62,55.12 39.62,50.04
  pour Bottom (isolate 0.305, rank 3): 28.45,0.25 56.64,0.25 56.64,56.64 27.18,56.64 27.18,52.58 30.99,52.58 30.99,39.88 25.4,33.53 25.4,7.24 28.45,7.24
  pour Top: 42.42,47.5 48.26,47.5 48.26,50.04 47.5,50.8 47.5,54.36 48.26,55.12 48.26,56.39 34.8,56.39 34.8,48.77 42.42,48.77
5V_ALT  (via drill 0.51)
  Top 0.254: C20.2 R24.2 13.59,15.28 13.59,15.37 v13.97,15.75 | 19.05,15.75 21.05,15.75 IC5.4
  Top 0.61: v13.97,15.75 19.05,15.75
  Bottom 0.61: v13.97,15.75 14.22,15.75 15.49,14.48 JP13.1
5V_SVO  (via drill 0.38, 0.51)
  Top 0.61: v17.65,10.16 v17.65,13.97
  Top 0.813: v20.83,5.97 22.99,5.97 J4.10 J5.10
  Bottom 0.406: JP8.2 17.27,4.32 | 5.59,6.86 5.71,6.86 6.35,6.22 6.35,6.35
  Bottom 0.61: JP12.2 JP13.2 17.14,14.48 v17.65,13.97 | 6.35,6.35 10.03,10.03 17.53,10.03 v17.65,10.16
  Bottom 0.813: JP4.2 JP3.2 JP2.2 JP1.2 4.32,8.13 5.59,6.86 8.13,4.32 JP5.2 JP6.2 JP7.2 JP8.2 | 17.27,4.32 18.92,5.97 v20.83,5.97
D+  (via drill 0.38)
  Top 0.254: IC3.43 42.19,25.3 v42.8,25.91 | J3.D+ 47.12,14.48 v46.74,14.86
  Bottom 0.254: v42.8,25.91 43.69,25.02 43.69,23.62 44.7,22.61 44.7,20.7 46.36,19.05 46.36,15.24 v46.74,14.86
D-  (via drill 0.38)
  Top 0.254: v46.74,13.59 46.83,13.68 J3.D- 48.72,13.69 | IC3.42 42.79,24.5 v42.8,24.51 | 48.85,13.72 48.79,13.72 48.74,13.66 48.72,13.69 | 48.72,13.69 48.77,13.69 48.84,13.77 47.96,13.77 47.88,13.69 48.72,13.69 | 48.72,13.69
  Bottom 0.254: v42.8,24.51 42.8,23.75 44.2,22.35 44.2,20.45 45.85,18.8 45.85,14.48 v46.74,13.59
DIR_1  (via drill 0.38)
  Top 0.254: LED1.A 13.32,33.53 13.83,33.02 v13.84,33.02 14.73,32.13 14.73,29.59 15.25,29.07 IC1.P$19 | IC3.5 35.6,29.3 35.65,29.3 v35.69,29.34
  Bottom 0.254: J4.6 34.8,4.45 37.08,6.73 37.08,16.13 35.31,17.91 35.31,18.67 35.69,19.05 v35.69,29.34 35.69,29.46 36.32,30.1 36.32,31.24 31.88,35.69 18.03,35.69 15.37,33.02 v13.84,33.02
DIR_2  (via drill 0.38)
  Top 0.254: IC3.3 37.2,25.79 v37.21,25.78 | 14.73,48.9 14.74,48.89 | 14.73,48.9 14.73,46.1 15.25,45.59 IC2.P$19 | 14.73,48.9 v13.97,49.66 13.59,50.04 13.59,50.03 12.7,50.03 LED2.A
  Bottom 0.254: v13.97,49.66 16.38,49.66 18.67,47.37 25.65,47.37 32.13,40.89 32.13,36.96 37.34,31.75 37.34,25.91 v37.21,25.78 37.21,23.11 36.7,22.61 36.7,19.05 38.1,17.65 38.1,5.08 J4.5
ENABLE_1  (via drill 0.38)
  Top 0.254: IC3.25 32.4,15.25 32.38,15.24 32.38,12.32 32.51,12.19 | 32.51,12.19 v32.77,11.94 | 32.51,12.19 29.97,12.19 29.72,12.45 29.72,15.11 29.21,15.62 27.94,15.62 27.18,16.38 27.18,21.72 | 27.18,21.72 27.18,22.48 v26.29,23.37 | R5.2 27.14,21.68 27.18,21.72 | IC1.P$2 14.75,20.46 v15.13,20.08
  Bottom 0.254: J4.7 32.26,11.43 v32.77,11.94 | v26.29,23.37 26.29,22.73 24.26,20.7 22.61,20.7 21.97,20.07 21.97,16.38 20.07,14.48 18.67,14.48 17.27,15.88 17.27,17.78 16.89,18.16 15.88,18.16 15.13,18.91 v15.13,20.08
ENABLE_2  (via drill 0.38)
  Top 0.254: R6.2 42.23,18.9 IC3.35 39.35,18.9 38.73,18.29 v36.2,18.29 | IC2.P$2 14.75,36.31 v15.11,35.94
  Bottom 0.254: J5.5 36.07,3.05 36.07,4.95 37.59,6.48 37.59,16.89 v36.2,18.29 36.2,28.7 36.83,29.34 36.83,31.5 32.13,36.2 15.37,36.2 v15.11,35.94
GND  (via drill 0.38)
  Top 0.254: J4.12 19.56,4.45 | 15.25,24.88 15.25,24.89 v15.75,24.89 | 15.25,41.65 15.25,41.4 v15.75,41.4
  Top 0.305: 15.25,21.09 IC1.P$3 15.25,24.76 | 15.25,24.76 15.24,24.77 | v15.75,26.92 IC1.P$18 15.75,32 | 15.24,41.66 15.25,41.65 IC2.P$3 15.25,37.85 15.24,37.85 | IC2.P$29 IC2.P$18 15.75,48.26 | 15.25,24.76 15.25,24.88
  Top 0.813: 8.13,1.78 JP8.1 J5.12 J4.12 19.56,6.22 | 1.78,7.24 1.78,19.05
  Bottom 0.61: J6.GND J6.P$4 46.09,35.06 | v45.47,32.89 45.47,34.44 46.09,35.06 | v45.47,37.85 45.47,35.69 46.09,35.06
  Bottom 0.813: 6.86,1.78 JP8.1 J5.12 J4.12 | 1.78,6.86 1.78,19.56
  other vias: 10.54,20.7 13.21,22.1 13.21,28.57 13.21,30.61 7.62,30.99 9.14,20.7 10.54,22.22 14.73,26.92 14.73,24.89 16.76,24.89 16.76,26.92 23.37,28.45 23.37,30.99 23.37,33.27 23.37,23.75 14.73,41.4 14.73,43.43 16.76,43.43 16.76,41.4 10.67,37.85 13.21,38.61 13.21,46.23 7.37,47.5 8.76,47.5 8,37.21 6.73,37.21 23.11,39.75 26.16,42.29 23.37,50.04 25.15,43.31 23.37,22.1 10.16,46.86 14.73,42.42 15.75,43.43 16.76,42.42 15.75,42.42 15.75,25.91 14.73,25.91 16.76,25.91
  pour Top (isolate 0.305, rank 3): 0.25,0.25 56.64,0.25 56.64,56.64 0.25,56.64
  pour Bottom (isolate 0.305, rank 2): 28.45,0.25 0.25,0.25 0.25,56.64 27.18,56.64 27.18,52.58 28.45,52.58 29.72,51.31 29.72,33.53 25.4,33.53 25.4,7.24 28.45,7.24
M1_OUT1A
  Top 0.305: 6.99,26.41 IC1.P$24
  Top 0.406: 6.99,26.41 6.36,26.41 JP9.2 4.19,27.18 2.92,28.45 2MM1.2
M1_OUT1B
  Top 0.254: 14.22,31.24 14.25,31.22
  Top 0.305: 14.12,31.34 14.22,31.24 | 14.25,31.22 IC1.P$21
  Top 0.406: 14.12,31.34 12.95,32.51 5.59,32.51 | 5.59,32.51 JP9.1 | 2MM1.1 3.05,32.26 3.3,32.51 5.59,32.51
M1_OUT2A
  Top 0.305: 6.99,25.41 IC1.P$26
  Top 0.406: 6.99,25.41 5.59,25.41 JP9.3 3.68,24.64 2MM1.3
M1_OUT2B
  Top 0.305: IC1.P$1 14.25,20.6 14.12,20.47
  Top 0.406: 14.12,20.47 13.21,19.56 8.13,19.56 JP9.4 3.81,22.1 2MM1.4
M2_OUT1A
  Top 0.305: 7.12,42.92 IC2.P$24
  Top 0.406: 5.59,42.92 7.12,42.92 | 5.59,42.92 JP10.2 | 2MM2.2 3.05,42.8 3.17,42.92 5.59,42.92
M2_OUT1B
  Top 0.254: 14.22,47.75 14.25,47.73
  Top 0.305: 14.12,47.86 14.22,47.75 | 14.25,47.73 IC2.P$21
  Top 0.406: 14.12,47.86 13.21,48.77 6.89,48.77 5.89,47.77 5.89,46.53 JP10.1 3.43,46.23 2MM2.1
M2_OUT2A
  Top 0.305: 7.12,41.92 IC2.P$26
  Top 0.406: 7.12,41.92 6.36,41.92 JP10.3 3.94,39.5 2MM2.3
M2_OUT2B
  Top 0.305: IC2.P$1 14.25,37.11 14.12,36.98
  Top 0.406: 14.12,36.98 13.21,36.07 5.59,36.07 | 5.59,36.07 JP10.4 | 5.59,36.07 3.56,36.07 2MM2.4
MCLR  (via drill 0.38)
  Top 0.254: IC1.P$12 23.25,26.41 23.26,26.42 23.26,26.43 24.64,27.81 24.64,29.08 26.67,31.11 v27.3,31.11 27.3,32.64 26.54,33.4 26.54,40.39 24.01,42.92 IC2.P$12 | v38.48,19.18 37.34,20.32 33.15,20.32 v32.89,20.07 31.24,20.07 30.01,21.3 IC3.18 | v28.57,52.45 28.57,52.71 J8.1 | R22.1 32.68,32.68 34.29,34.29 34.29,35.94 SW2.3 34.16,37.47 v33.53,38.1
  Bottom 0.254: v28.57,52.45 29.08,52.45 29.46,52.07 30.35,52.07 30.48,51.94 30.48,44.07 33.53,41.02 v33.53,38.1 33.53,37.08 38.35,32.26 38.35,27.69 39.12,26.92 39.12,25.65 38.23,24.77 38.23,22.61 37.72,22.1 37.72,19.94 v38.48,19.18 | v27.3,31.11 28.32,30.1 30.1,30.1 33.53,26.67 33.53,20.7 v32.89,20.07
MS1  (via drill 0.38)
  Top 0.254: IC1.P$9 23.86,24.91 23.88,24.89 v24.77,24.89 | IC2.P$9 22.84,41.42 24.64,39.62 v24.64,32.77 | IC3.27 34,17.31 33.91,17.4 v33.91,17.78
  Bottom 0.254: v24.77,24.89 24.77,26.04 24.51,26.29 24.51,27.05 24.64,27.18 v24.64,32.77 24.64,32.8 25.49,33.66 27.05,33.66 29.59,31.11 30.61,31.11 34.54,27.18 34.54,19.43 34.29,19.18 34.29,18.16 v33.91,17.78
MS2  (via drill 0.38)
  Top 0.254: IC1.P$10 23.87,25.41 23.88,25.4 25.15,26.67 v25.4,26.67 | IC2.P$10 23.23,41.92 25.53,39.62 v25.53,31.5 | IC3.26 33.2,17.22 33.02,17.4 33.02,18.54 v33.4,18.92
  Bottom 0.254: v33.4,18.92 33.4,19.05 34.04,19.68 34.04,26.92 30.35,30.61 29.34,30.61 26.8,33.15 26.07,33.15 25.53,32.61 v25.53,31.5 25.15,31.11 25.15,26.92 v25.4,26.67
MS3  (via drill 0.38)
  Top 0.254: IC1.P$11 23.49,25.91 25.15,27.56 25.15,28.32 v26.42,29.59 | IC2.P$11 23.62,42.42 26.04,40.01 26.04,32.64 v26.42,32.26 | IC3.31 37.21,16.31 37.21,15.24 36.96,14.99 36.96,12.32 v35.69,11.05
  Bottom 0.254: v26.42,32.26 v26.42,29.59 29.84,29.59 33.02,26.42 33.02,21.46 32,20.45 32,19.68 32.51,19.18 32.51,18.54 33.02,18.03 33.02,17.4 33.53,16.89 34.8,16.89 36.07,15.62 36.07,11.43 v35.69,11.05
N$1
  Bottom 0.406: 15.37,14.48 16.64,14.48
N$2
  Top 0.61: F1.1 38.48,44.83 38.54,44.89 | 38.54,44.89 41.15,47.5 41.15,48.13 41.02,48.26 D3.C | D2.C 39.88,39.87 39.88,42.42 38.73,43.56 38.73,44.7 38.54,44.89
N$3
  Top 0.254: C2.1 17.65,20.32 15.75,22.22 IC1.P$4
N$4
  Top 0.254: R13.2 R14.1 R18.1
N$5
  Top 0.254: IC1.P$5 16.25,22.49 17.53,21.21 21.34,21.21 21.59,20.95 21.59,20.41 C2.2
N$6
  Top 0.406: 52.58,36.07 J7.VIN0
  Top 0.813: 52.58,36.07 49.53,39.12 43.82,39.12 41.91,41.02 41.93,41.04 D1.A
N$7
  Bottom 0.406: D4.A 41.66,41.17
  Bottom 0.61: J6.VIN0 52.58,45.09 51.18,43.69 42.55,43.69 41.66,42.8 41.66,41.17
N$8
  Top 0.254: IC5.1 12.41,17.39 R19.1 12.15,16.6 11.94,16.38 R24.1
N$9
  Top 0.254: R27.1 R23.1 33.87,53.59 34.54,53.59 35.81,54.86 IC4.1
N$10  (via drill 0.51)
  Top 0.61: v35.94,40.64 32.38,40.64 30.99,39.24 30.99,37.59 v30.73,37.34
  Bottom 0.254: 37.59,41.15 D4.C
  Bottom 0.61: 37.59,41.15 36.45,41.15 v35.94,40.64 | v30.73,37.34 30.61,37.21 14.86,37.21 10.54,32.89 10.54,30.35 8,27.81 8,19.56 10.54,17.02 JP12.1
N$16
  Top 0.254: IC2.P$4 15.75,38.61 18.29,36.07 C4.1
N$17
  Top 0.254: IC2.P$5 16.25,39 18.29,36.96 20.79,36.96 C4.2
N$19
  Top 0.254: IC1.P$13 19.03,26.91 19.94,27.81 19.94,28.41
  Top 0.305: 19.94,28.41 R8.1
N$20
  Top 0.254: IC1.P$8 19.32,24.41 C10.1
N$21
  Top 0.254: IC1.P$6 16.75,22.75 17.4,22.1 C5.1
N$26
  Top 0.254: LED2.C 11.19,51.21 R16.2
N$27
  Top 0.254: PWR.A R20.1
N$29
  Top 0.254: USB.A 54.6,30.89 R26.1
N$30
  Top 0.254: USR.A 54.6,23.47 R25.1
N$31
  Top 0.254: 8.69,24.91 8.69,24.78 8.59,24.78
  Top 0.305: 8.69,24.91 IC1.P$27
  Top 0.406: 8.59,24.78 8.59,24.68 R3.2
N$32
  Top 0.254: 8.82,26.91 8.72,26.91 8.72,27.01 R1.2
  Top 0.305: 8.82,26.91 IC1.P$23
N$35
  Top 0.254: 11.19,33.55 LED1.C R15.2
N$36
  Top 0.406: IC4.3 37.34,50.3
  Top 0.61: 37.34,50.3 F1.2 | C15.2 35.27,49.22 IC4.3
N$41
  Top 0.254: IC2.P$6 16.75,39.26 17.65,38.35 C6.1
N$43
  Top 0.254: 8.82,43.42 8.72,43.42 8.72,43.52 R2.2
  Top 0.305: 8.82,43.42 IC2.P$23
N$44
  Top 0.254: 8.82,41.42 8.72,41.42 8.72,41.32 R4.2
  Top 0.305: 8.82,41.42 IC2.P$27
N$45
  Top 0.254: IC2.P$8 19.45,40.92 C9.1
N$48
  Top 0.254: IC2.P$13 19.29,43.42 19.94,44.07 19.94,44.92
  Top 0.305: 19.94,44.92 R7.1
PRG_SW
  Top 0.254: SW1.2 39.66,13.84 R21.1 40.43,16.89 40.01,16.89 39.37,17.53 36.7,17.53 36.4,17.22 IC3.30
RA1  (via drill 0.38)
  Top 0.254: 28.98,19.68 IC3.20 29.83,19.7 30.48,19.05 v30.48,17.91
  Bottom 0.254: v30.48,17.91 31.24,17.14 31.24,5.97 29.72,4.45 J4.8
RA2  (via drill 0.38)
  Top 0.254: IC3.21 28.17,18.9 27.69,18.41 27.69,16.64 28.19,16.13 29.34,16.13 v29.72,16.51
  Bottom 0.254: v29.72,16.51 30.73,15.49 30.73,7.24 28.45,4.95 28.45,3.05 J5.8
RA3  (via drill 0.38)
  Top 0.254: IC3.22 29,17.31 v28.7,17.02
  Bottom 0.254: v28.7,17.02 28.7,16.26 30.23,14.73 30.23,7.49 27.18,4.45 J4.9
RA5  (via drill 0.38)
  Top 0.254: IC3.24 31.6,17.42 31.65,17.42 v32,17.78
  Bottom 0.254: v32,17.78 31.75,17.53 31.75,5.71 30.99,4.95 30.99,3.05 J5.7
RB0  (via drill 0.38)
  Top 0.254: IC3.8 33.2,23.98 v32.21,22.99
  Bottom 0.254: JP2.3 7.24,11.56 20.32,11.56 24.13,15.37 24.13,18.29 28.57,22.73 28.57,24.94 29.92,26.29 31.75,26.29 32.51,25.53 32.51,23.29 v32.21,22.99
RB1  (via drill 0.51)
  Top 0.254: IC3.9 32.4,25.16 TP6.P$1
  Bottom 0.254: JP1.3 8.38,11.05 20.57,11.05 24.64,15.11 24.64,18.03 29.08,22.48 29.08,24.77 30.1,25.78 31.11,25.78 31.5,25.4 TP6.P$1
  other vias: 31.5,24.26
RB2  (via drill 0.38)
  Top 0.254: IC3.10 31.6,26.77 31.37,26.54 30.35,26.54 29.72,27.18 v29.46,27.18
  Bottom 0.254: v29.46,27.18 29.46,26.54 28.07,25.15 28.07,22.99 23.62,18.54 23.62,15.62 20.07,12.07 9.27,12.07 JP3.3
RB3  (via drill 0.38)
  Top 0.254: IC3.11 30.14,27.9 v29.46,28.57
  Bottom 0.254: v29.46,28.57 28.57,27.69 28.57,26.42 27.56,25.4 27.56,23.24 23.11,18.8 23.11,15.88 19.81,12.57 9.65,12.57 8.25,13.97 8.25,15.62 JP4.3
RB4  (via drill 0.38)
  Top 0.254: IC3.14 29.93,24.5 v30.43,24.99
  Bottom 0.254: JP5.3 9.91,6.86 12.32,9.27 19.56,9.27 25.15,14.86 25.15,17.78 29.59,22.22 29.59,24.15 v30.43,24.99
RB5  (via drill 0.38)
  Top 0.254: IC3.15 30.23,23.7 v30.43,23.49
  Bottom 0.254: JP6.3 12.45,6.86 14.35,8.76 19.81,8.76 25.65,14.61 25.65,17.53 30.1,21.97 30.1,23.16 v30.43,23.49
RB6  (via drill 0.38)
  Top 0.254: v39.12,24.38 36.2,21.46 32.51,21.46 31.62,22.35 v30.99,22.35 30.48,22.35 29.93,22.9 IC3.16
  Bottom 0.254: v39.12,24.38 39.62,24.89 39.62,27.18 38.86,27.94 38.86,32.51 34.42,36.96 34.42,40.89 31.11,44.2 31.11,52.07 30.61,52.58 29.72,52.58 28.96,53.34 24.26,53.34 23.88,53.72 22.22,53.72 J8.5 | v30.99,22.35 30.99,22.1 26.16,17.27 26.16,14.35 20.07,8.25 16.38,8.25 14.99,6.86 JP7.3
RB7  (via drill 0.38)
  Top 0.254: v39.12,23.11 36.96,20.95 31.62,20.95 v31.37,21.21 30.86,21.21 29.97,22.1 IC3.17
  Bottom 0.254: v39.12,23.11 40.13,24.13 40.13,27.43 39.37,28.19 39.37,32.77 34.93,37.21 34.93,41.15 31.75,44.32 31.75,52.2 30.86,53.09 29.97,53.09 29.21,53.85 24.64,53.85 J8.4 | v31.37,21.21 30.86,21.21 26.67,17.02 26.67,14.1 19.43,6.86 JP8.3
RC0  (via drill 0.38)
  Top 0.254: IC3.32 38,15.14 37.47,14.61 37.47,13.08 40.39,10.16 v40.39,9.65
  Bottom 0.254: v40.39,9.65 39.5,8.76 39.5,4.7 J4.4
RC2  (via drill 0.38)
  Top 0.254: IC3.36 39.23,19.7 v38.61,20.32 | v40.26,30.99 R14.2
  Bottom 0.254: J5.3 41.15,3.05 41.15,5.08 40.64,5.59 40.64,8.38 41.4,9.14 41.4,10.29 40.13,11.56 40.13,18.8 v38.61,20.32 38.23,20.7 38.23,21.72 38.73,22.22 39.88,22.22 40.64,22.99 40.64,27.69 40.13,28.19 40.13,30.86 v40.26,30.99
RC6  (via drill 0.38)
  Top 0.254: v42.16,26.92 42.16,26.67 41.59,26.1 IC3.44
  Bottom 0.254: v42.16,26.92 41.91,26.67 41.91,23.62 42.93,22.61 42.93,21.59 42.16,20.83 42.16,16.13 44.58,13.72 44.58,11.05 46.23,9.4 46.23,3.05 J5.1
RC7  (via drill 0.38)
  Top 0.254: 38.8,27.88 IC3.1 38.86,27.83 38.86,28.57 v41.02,28.57 | R12.2 42.8,10.71 42.8,13.17 R17.1 42.71,13.08 v41.53,13.08
  Bottom 0.254: v41.02,28.57 41.15,28.45 41.15,13.46 v41.53,13.08 41.53,12.45 43.69,10.29 43.69,3.05 J5.2
RD0  (via drill 0.38)
  Top 0.254: IC3.38 39.15,21.3 v39.12,21.34
  Bottom 0.254: v39.12,21.34 40.64,19.81 40.64,11.81 41.91,10.54 41.91,8.89 41.15,8.13 41.15,5.97 42.42,4.7 J4.3
RD1  (via drill 0.38)
  Top 0.254: v42.04,22.1 IC3.39
  Bottom 0.254: v42.04,22.1 41.66,21.72 41.66,15.88 44.07,13.46 44.07,10.8 44.96,9.91 J4.2
REF_RA0  (via drill 0.38)
  Top 0.254: IC1.P$17 16.25,29.46 v17.14,30.35 | v17.4,47.37 17.4,46.99 16.26,45.85 IC2.P$17 | v31.37,18.8 31.37,19.05 29.92,20.5 IC3.19 28.02,20.5 27.69,20.83 27.69,23.49 v26.67,24.51 | v26.04,27.81 27.3,29.08 27.3,29.84 28.19,30.73 28.19,31.5 27.81,31.88 27.81,33.02 27.05,33.78 27.05,34.8 | 27.05,34.8 27.05,40.39 v27.43,40.77 | 27.05,34.8 v28.57,34.8 | R11.2 27,11.76 25.91,10.67 TP3.1
  Bottom 0.254: v17.14,30.35 17.14,34.04 18.29,35.18 28.19,35.18 v28.57,34.8 | v27.43,40.77 27.43,44.83 25.4,46.86 17.91,46.86 v17.4,47.37 | v31.37,18.8 29.21,18.8 27.81,17.4 27.81,16.38 29.72,14.48 29.72,11.68 | 29.72,11.68 29.72,7.75 27.94,5.97 26.92,5.97 25.91,4.95 25.91,3.05 J5.9 | v26.67,24.51 26.67,27.18 v26.04,27.81 | 29.72,11.68 29.59,11.81 27.05,11.81 25.91,10.67 TP3.1
SLEEP_1
  Top 0.254: IC1.P$14 18.77,27.41 18.92,27.56 18.92,29.08 19.94,30.1 19.94,30.99 R9.2
SLEEP_2
  Top 0.254: IC2.P$14 18.92,44.7 18.92,45.59 19.94,46.61 19.94,47.5 R10.2
STEP_1  (via drill 0.38)
  Top 0.254: v35.43,30.99 36.58,29.84 36.58,28.96 36.4,28.78 IC3.4 | IC1.P$16 16.75,29.07 17.02,29.34 17.53,29.34 18.16,29.97 v18.16,31.24
  Bottom 0.254: v18.16,31.24 18.16,32.77 17.78,33.15 17.78,33.91 18.54,34.67 27.56,34.67 28.32,33.91 28.96,33.91 30.1,35.05 31.75,35.05 35.43,31.37 v35.43,30.99 35.43,30.86 34.8,30.23 34.8,27.69 35.18,27.3 35.18,19.3 34.8,18.92 34.8,17.65 36.58,15.88 36.58,8 33.53,4.95 33.53,3.05 J5.6
STEP_2  (via drill 0.38)
  Top 0.254: v18.29,49.02 18.29,47.12 16.75,45.58 IC2.P$16 | IC3.2 38,26.64 v38.23,26.42
  Bottom 0.254: v18.29,49.02 19.43,47.88 25.91,47.88 32.64,41.15 32.64,37.21 37.85,32 37.85,26.8 v38.23,26.42 38.23,25.53 37.72,25.02 37.72,22.86 37.21,22.35 37.21,19.3 38.61,17.91 38.61,3.05 J5.4
USB_LED  (via drill 0.38)
  Top 0.254: IC3.41 43.51,23.7 45.21,25.4 v45.21,25.91 | R26.2 53,32.35 v52.96,32.38
  Bottom 0.254: v45.21,25.91 45.21,30.86 46.61,32.26 52.96,32.26 v52.96,32.38
USR_LED  (via drill 0.38)
  Top 0.254: IC3.40 43.47,22.9 v46.48,25.91 | v53.85,22.1 53.34,22.1 52.96,22.48 52.96,23.33 R25.2
  Bottom 0.254: v46.48,25.91 50.04,25.91 v53.85,22.1
V+  (via drill 0.38, 0.51)
  Top 0.254: v23.37,38.35 C6.2 | 11.94,24.41 C7.1 | 11.94,27.41 C8.1 | 37.47,41.15 D1.C 38.08,41.4 | C5.2 21.72,22.1 22.99,20.83 v22.99,19.81 | C21.2 13.63,11.21 14.48,12.07 14.48,12.81 IC5.3
  Top 0.305: IC1.P$28 11.94,24.41 11.2,24.41 v10.67,23.88 | IC1.P$22 11.94,27.41 11.2,27.41 v10.67,27.94 | 11.94,40.92 11.2,40.92 v10.67,40.39 | 11.94,40.92 IC2.P$28 | 11.94,40.92 C11.1 | 11.94,43.92 11.33,43.92 v10.67,44.58 | 11.94,43.92 IC2.P$22 | 11.94,43.92 C12.1
  Top 0.406: v9.4,30.61 9.4,30.1 10.67,28.83 v10.67,27.94 | v10.67,40.39 10.67,39.5 9.4,38.23 v9.4,37.59
  Top 0.61: IC5.3 14.5,13.82 v13.97,14.35 | R13.1 41.57,33.49 41.15,33.91 D2.A 41.15,35.18 37.83,38.5 D1.C
  Top 0.813: 37.47,41.15 36.2,42.42 30.85,42.42 29.71,41.28 | 28.45,38.1 C14.+ 28.45,40.02 29.71,41.28 | 29.71,41.28 29.72,41.28 v29.59,41.15
  Bottom 0.254: v22.99,19.81 22.99,19.43 22.61,19.05 22.61,16.13 19.56,13.08 15.24,13.08 v13.97,14.35 | 23.37,38.23 v23.37,38.35
  Bottom 0.406: v10.67,27.94 v10.67,23.88 | v10.67,40.39 v10.67,44.58
  Bottom 0.61: v9.4,37.59 9.4,34.54 v9.4,30.61 7.11,28.32 7.11,19.18 11.94,14.35 v13.97,14.35
  Bottom 0.813: 9.4,34.54 10.8,34.54 14.48,38.23 23.37,38.23 26.67,38.23 v29.59,41.15
VBUS  (via drill 0.38, 0.51)
  Top 0.254: J3.VBUS | J3.VBUS 48.77,12.83 | J3.VBUS 47.3,12.88 45.09,10.67 R12.1
  Top 0.406: 48.77,12.83 50.16,12.83 v51.31,13.97 | D3.A 42.04,44.07 v44.32,41.78
  Bottom 0.406: v51.31,13.97 48.77,16.51 48.77,19.56 44.32,24 44.32,30.86 41.4,33.78 41.4,37.34 44.32,40.26 v44.32,41.78
VCAP
  Top 0.254: IC3.23 30.8,13.53 C13.A

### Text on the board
Top: schmalzhaus.com/EBB | EiBot | Board
Bottom: 8/20/2011
tPlace: GND | 3.3V | schmalzhaus.com/EBB | ICSP | PWR | IN | DIR2 | 3.3V | 9-30VDC | MOTOR2 | RST | DIR1 | CURRENT | ADJ | USB | EBB | MOTOR1 | USR | EiBot | Board | B3 | B2 | B0 | PRG | TP3 | B1 | B4 | B5 | B6 | B7 | A3 | A1 | E0 | D7 | D5 | C0 | D0 | D1 | GND | GND | 5V | 5V | A0 | A2 | A5 | D6 | C1 | D4 | C2 | C7 | C6 | GND | 3.3V | 5V | J4 | GND | GND | J5
bPlace: GND | 3.3V | PGC(RB6) | PGD(RB7) | GND | 3.3V | MCLR | MOTOR 2 | ICSP | 4-6V DC | EiBotBoard | Released under Creative | Commons V3.0 Attribution | Licence by SchmalzHaus | for more information see: | www.schmalzhaus.com/EBB | MOTOR 1 | JP12 | JP13 | Pen | Servos | B3 | Arm | B2 | B0 | B1 | B4 | GND | 3.3V | 5V | A3 | A1 | E0 | D7 | D5 | C0 | D0 | D1 | GND | B5 | B6 | B7 | IO PINS | 5V | GND | 3.3V | 5V | A0 | A2 | A5 | D6 | C1 | D4 | C2 | C7 | C6 | J4 | GND | 5V | GND | J5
